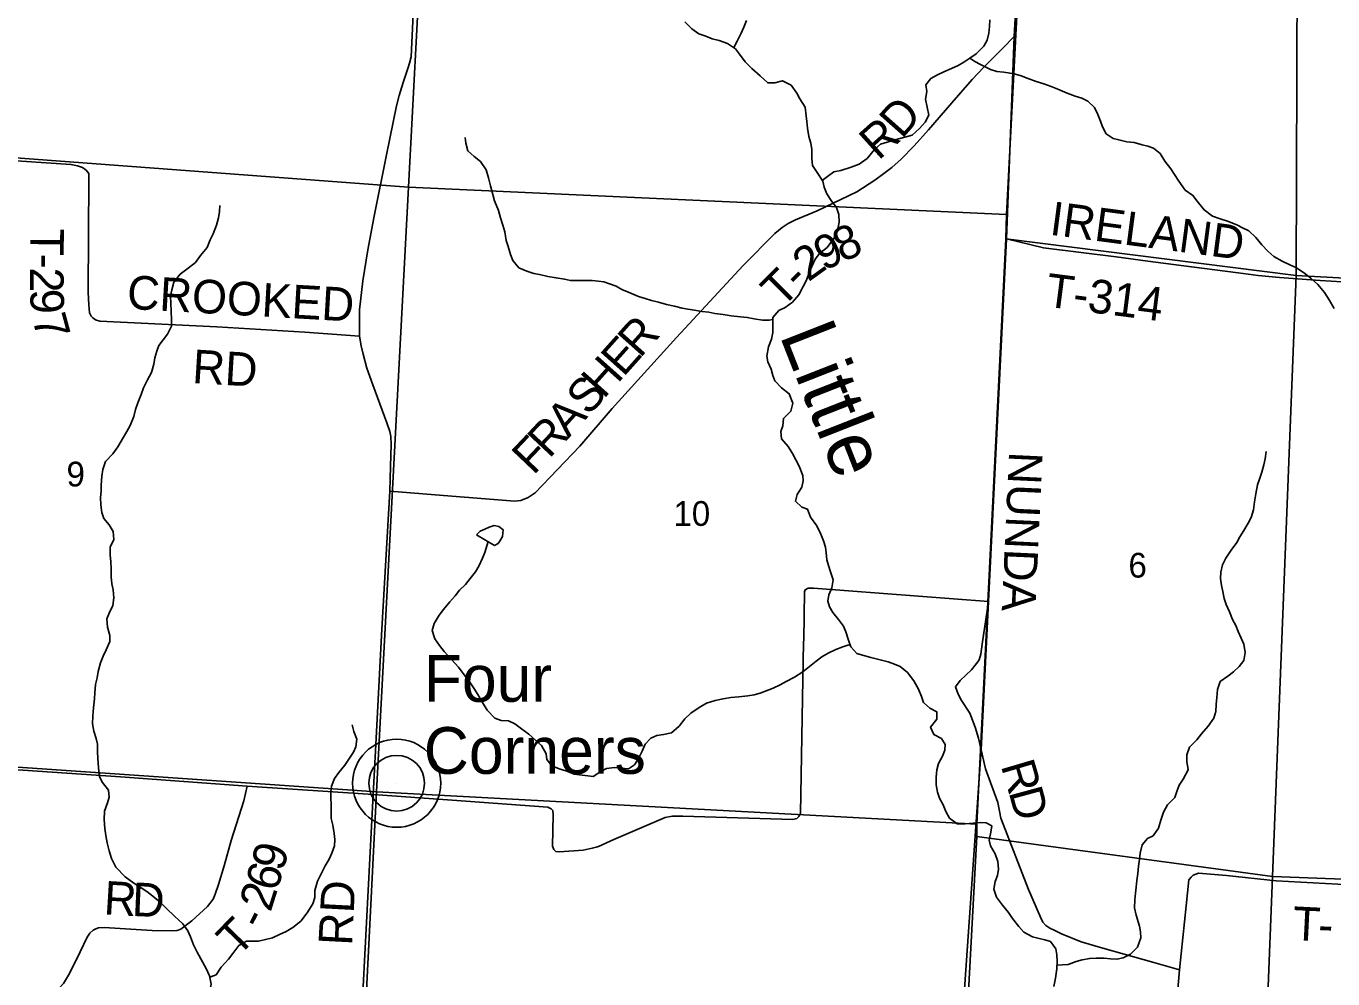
# Model space of a CAD drawing. Extents: x 1759416 to 2214760, y 252598 to 1116833.
# Drawn here: x 1998256 to 2009925, y 911621 to 920128 of the extents above; entities that cross this region are included whole.
import ezdxf

# ---------------------------------------------------------------- set-up
doc = ezdxf.new("R2010")
doc.units = 0
for name, color, linetype in [('GM_X_County_Road', 7, 'Continuous'), ('GM_X_County_Road_Text', 7, 'Continuous'), ('GM_X_Minor_Lake', 7, 'Continuous'), ('GM_X_Minor_River', 7, 'Continuous'), ('GM_X_Minor_River_Text', 7, 'Continuous'), ('GM_X_Section', 7, 'Continuous'), ('GM_X_Section_Text', 7, 'Continuous'), ('GM_X_Township', 7, 'Continuous'), ('GM_X_Township_Road', 7, 'Continuous'), ('GM_X_Township_Road_Text', 7, 'Continuous'), ('GM_X_Unincorporated', 7, 'Continuous'), ('GM_X_Unincorporated_Location', 7, 'Continuous'), ('GM_X_Unincorporated_Text', 7, 'Continuous')]:
    doc.layers.add(name, color=color, linetype=linetype)

msp = doc.modelspace()

# ---------------------------------------------------------------- linework, layer by layer
at = {"layer": 'GM_X_County_Road'}
for points in [[(2006766, 914471), (2006782, 914521), (2006794, 914611), (2006850, 914992), (2007010, 918229), (2007080, 920037), (2007121, 920797), (2007263, 923436), (2007268, 923555)], [(2001192, 910125), (2001356, 913267), (2001379, 913714), (2001432, 914744), (2001505, 915975), (2001510, 916196), (2001517, 916394), (2001514, 916463), (2001504, 916509), (2001477, 916585), (2001351, 916925), (2001300, 917074), (2001265, 917198), (2001247, 917275), (2001232, 917359), (2001232, 917425), (2001234, 917596), (2001263, 917854), (2001307, 918131), (2001364, 918431), (2001473, 918980), (2001563, 919416), (2001587, 919509), (2001624, 919625), (2001669, 919759), (2001681, 919799), (2001694, 919855), (2001719, 920366)], [(2008491, 910937), (2008556, 911703), (2008327, 911768), (2007871, 911894), (2007678, 911951), (2007502, 912024), (2007436, 912055), (2007398, 912075), (2007363, 912099), (2007335, 912127), (2007313, 912172), (2007207, 912420), (2006959, 913055), (2006933, 913196), (2006822, 913496), (2006784, 913665), (2006760, 913769), (2006731, 913868), (2006683, 913993), (2006608, 914108), (2006579, 914163), (2006555, 914230), (2006596, 914284), (2006697, 914379), (2006731, 914423), (2006753, 914452), (2006765, 914469), (2006766, 914471)]]:
    msp.add_lwpolyline(points, dxfattribs=at)
at = {"layer": 'GM_X_Minor_Lake'}
for points in [[(2002440, 915492), (2002472, 915510), (2002488, 915534), (2002509, 915571), (2002515, 915631), (2002477, 915659), (2002435, 915668), (2002391, 915654), (2002353, 915636), (2002311, 915620), (2002279, 915586)], [(2002279, 915586), (2002440, 915492)]]:
    msp.add_lwpolyline(points, dxfattribs=at)
at = {"layer": 'GM_X_Minor_River'}
for points in [[(2004138, 920168), (2004202, 920104), (2004264, 920060), (2004326, 920040), (2004382, 920016), (2004446, 920000), (2004518, 919973), (2004590, 919927), (2004626, 919877), (2004678, 919809), (2004736, 919751), (2004812, 919685), (2004878, 919621), (2004942, 919623), (2005010, 919641), (2005088, 919601), (2005138, 919531), (2005164, 919478), (2005214, 919404), (2005222, 919328), (2005228, 919278), (2005234, 919216), (2005246, 919144), (2005262, 919084), (2005272, 919026), (2005272, 918946), (2005279, 918884), (2005319, 918820), (2005369, 918744), (2005383, 918689), (2005405, 918631), (2005451, 918563), (2005491, 918509), (2005513, 918445), (2005515, 918377), (2005497, 918293), (2005469, 918231), (2005409, 918153), (2005343, 918101), (2005303, 918047), (2005272, 917981), (2005248, 917929), (2005224, 917859), (2005194, 917803), (2005156, 917730), (2005100, 917664), (2005034, 917616), (2004978, 917588), (2004924, 917528), (2004923, 917462), (2004925, 917392), (2004911, 917334), (2004885, 917264), (2004871, 917182), (2004879, 917132), (2004909, 917064), (2004925, 917010), (2004941, 916960), (2005001, 916900), (2005071, 916846), (2005103, 916761), (2005085, 916689), (2005019, 916625), (2005013, 916559), (2004995, 916509), (2005002, 916443), (2005060, 916375), (2005100, 916313), (2005130, 916257), (2005160, 916199), (2005192, 916117), (2005196, 916067), (2005182, 916012), (2005140, 915946), (2005126, 915886), (2005184, 915834), (2005234, 915816), (2005260, 915744), (2005318, 915666), (2005354, 915592), (2005376, 915532), (2005394, 915476), (2005400, 915426), (2005406, 915364), (2005420, 915312), (2005438, 915257)], [(2004575, 919937), (2004606, 919993), (2004642, 920066), (2004666, 920120), (2004688, 920178)], [(2005365, 918751), (2005411, 918786), (2005470, 918828), (2005532, 918840), (2005624, 918868), (2005694, 918897), (2005766, 918947), (2005832, 919028), (2005886, 919074), (2006026, 919116), (2006103, 919138), (2006167, 919155), (2006233, 919214), (2006283, 919272), (2006317, 919334), (2006301, 919404), (2006287, 919476), (2006299, 919544), (2006291, 919604), (2006335, 919662), (2006394, 919692), (2006450, 919720), (2006520, 919750), (2006578, 919776), (2006630, 919806), (2006684, 919842), (2006740, 919882), (2006808, 919948), (2006838, 920002), (2006852, 920066), (2006858, 920124), (2006863, 920184)], [(2006684, 919842), (2006728, 919812), (2006778, 919786), (2006868, 919740), (2006924, 919724), (2006986, 919718), (2007042, 919708), (2007092, 919700), (2007142, 919685), (2007196, 919665), (2007276, 919635), (2007344, 919613), (2007410, 919589), (2007469, 919565), (2007551, 919529), (2007625, 919503), (2007683, 919485), (2007737, 919459), (2007797, 919403), (2007825, 919339), (2007851, 919279), (2007867, 919228), (2007899, 919168), (2007963, 919124), (2008013, 919112), (2008085, 919096), (2008149, 919090), (2008221, 919068), (2008273, 919056), (2008323, 919038), (2008383, 918990), (2008425, 918922), (2008477, 918854), (2008511, 918802), (2008549, 918743), (2008607, 918665), (2008675, 918617), (2008713, 918565), (2008775, 918487), (2008851, 918431), (2008917, 918409), (2008985, 918387), (2009067, 918355), (2009117, 918327), (2009175, 918299), (2009237, 918240), (2009291, 918176), (2009345, 918120), (2009399, 918072), (2009473, 918030), (2009539, 917998), (2009593, 917974), (2009661, 917928), (2009727, 917878), (2009789, 917822), (2009849, 917749), (2009891, 917683), (2009937, 917607)], [(2003312, 917858), (2003116, 917857), (2003064, 917869), (2002988, 917880), (2002914, 917894), (2002839, 917910), (2002789, 917919), (2002727, 917939), (2002657, 917971), (2002601, 918035), (2002582, 918089), (2002560, 918161), (2002544, 918215), (2002530, 918293), (2002513, 918351), (2002493, 918417), (2002473, 918483), (2002440, 918567), (2002424, 918625), (2002402, 918701), (2002385, 918775), (2002365, 918845), (2002315, 918919), (2002258, 918965), (2002200, 919014), (2002184, 919082), (2002176, 919133)], [(1999985, 918528), (1999983, 918474), (1999973, 918416), (1999956, 918352), (1999926, 918273), (1999900, 918219), (1999872, 918153), (1999813, 918080), (1999769, 918018), (1999703, 917966), (1999633, 917915), (1999574, 917843), (1999556, 917775), (1999546, 917719), (1999548, 917649), (1999551, 917589), (1999555, 917500), (1999555, 917448), (1999518, 917378), (1999480, 917328), (1999442, 917276), (1999424, 917225), (1999406, 917167), (1999397, 917109), (1999375, 917035), (1999341, 916969), (1999305, 916900), (1999284, 916838), (1999254, 916766), (1999234, 916706), (1999217, 916644), (1999185, 916563), (1999157, 916509), (1999127, 916459), (1999074, 916371), (1999030, 916308), (1998966, 916242), (1998942, 916170), (1998933, 916110), (1998927, 916029), (1998925, 915975), (1998921, 915919), (1998922, 915853), (1998932, 915785), (1998950, 915733), (1998997, 915675), (1999035, 915615), (1999041, 915543), (1999007, 915475), (1999008, 915403), (1999012, 915349), (1999016, 915283), (1999017, 915211), (1999021, 915147), (1999033, 915094), (1999040, 915022), (1999030, 914956), (1998998, 914886), (1998978, 914836), (1998983, 914760), (1999003, 914688), (1999003, 914632), (1998971, 914559), (1998944, 914503), (1998920, 914443), (1998900, 914367), (1998891, 914309), (1998877, 914249), (1998869, 914176), (1998867, 914122), (1998858, 914040), (1998852, 913970), (1998850, 913898), (1998861, 913832), (1998883, 913768), (1998893, 913716), (1998895, 913646), (1998898, 913596), (1998900, 913544), (1998906, 913476), (1998912, 913425), (1998939, 913373), (1998991, 913306), (1998997, 913244), (1998983, 913193), (1998956, 913119), (1998954, 913043), (1998960, 912963), (1998969, 912901), (1998981, 912835), (1998997, 912763), (1999018, 912695), (1999058, 912617), (1999142, 912531), (1999217, 912475), (1999285, 912434), (1999335, 912400), (1999389, 912358), (1999456, 912304), (1999510, 912248), (1999582, 912181)], [(2004924, 917510), (2004892, 917504), (2004831, 917504), (2004757, 917516), (2004695, 917527), (2004635, 917533), (2004551, 917541), (2004479, 917553), (2004407, 917563), (2004353, 917573), (2004291, 917579), (2004225, 917591), (2004165, 917601), (2004115, 917611), (2004045, 917627), (2003975, 917643), (2003903, 917663), (2003841, 917679), (2003783, 917695), (2003725, 917713), (2003640, 917749), (2003576, 917778), (2003526, 917806), (2003466, 917828), (2003416, 917844), (2003364, 917852), (2003312, 917858)], [(2007461, 911742), (2007562, 911750), (2007632, 911776), (2007686, 911790), (2007754, 911804), (2007812, 911806), (2007884, 911806), (2007940, 911800), (2007996, 911796), (2008051, 911808), (2008119, 911842), (2008179, 911904), (2008211, 911988), (2008207, 912042), (2008197, 912092), (2008167, 912190), (2008153, 912254), (2008157, 912328), (2008163, 912386), (2008167, 912440), (2008173, 912500), (2008183, 912563), (2008190, 912627), (2008198, 912689), (2008204, 912743), (2008222, 912817), (2008270, 912873), (2008320, 912899), (2008368, 912967), (2008390, 913039), (2008412, 913111), (2008448, 913175), (2008513, 913241), (2008531, 913293), (2008551, 913351), (2008587, 913405), (2008633, 913487), (2008621, 913561), (2008621, 913620), (2008645, 913690), (2008711, 913756), (2008751, 913810), (2008812, 913878), (2008862, 913948), (2008880, 914008), (2008884, 914072), (2008888, 914132), (2008896, 914204), (2008918, 914276), (2008986, 914324), (2009036, 914364), (2009088, 914410), (2009131, 914464), (2009143, 914536), (2009131, 914610), (2009107, 914664), (2009079, 914722), (2009057, 914775), (2009029, 914831), (2009003, 914899), (2008973, 914965), (2008953, 915017), (2008941, 915079), (2008931, 915133), (2008921, 915195), (2008923, 915253), (2008939, 915319), (2008969, 915379), (2009016, 915449), (2009068, 915517), (2009094, 915567), (2009130, 915625), (2009168, 915690), (2009196, 915742), (2009216, 915810), (2009224, 915880), (2009236, 915952), (2009252, 916032), (2009271, 916084), (2009289, 916146), (2009309, 916212), (2009321, 916264), (2009329, 916330)], [(2003321, 913429), (2003149, 913448), (2003075, 913480), (2003015, 913496), (2002951, 913522), (2002906, 913579), (2002900, 913629), (2002858, 913705), (2002808, 913749), (2002745, 913805), (2002681, 913855), (2002619, 913897), (2002563, 913924), (2002499, 913928), (2002442, 913950), (2002372, 914020), (2002332, 914088), (2002291, 914160), (2002253, 914217), (2002219, 914269), (2002169, 914337), (2002116, 914405), (2002054, 914473), (2001990, 914543), (2001947, 914597), (2001905, 914657), (2001883, 914733), (2001900, 914793), (2001944, 914869), (2001984, 914919), (2002040, 914988), (2002087, 915040), (2002127, 915092), (2002179, 915143), (2002221, 915197), (2002269, 915255), (2002298, 915305), (2002332, 915378), (2002352, 915428), (2002381, 915526)], [(2005438, 915257), (2005462, 915183), (2005451, 915113), (2005423, 915051), (2005415, 914993), (2005429, 914943), (2005459, 914893), (2005511, 914829), (2005555, 914769), (2005577, 914719), (2005599, 914645), (2005621, 914587), (2005675, 914526), (2005725, 914510), (2005799, 914490), (2005893, 914466), (2005955, 914452), (2006011, 914430), (2006061, 914410), (2006125, 914356), (2006183, 914282), (2006225, 914208), (2006251, 914142), (2006269, 914088), (2006325, 914037), (2006389, 914005), (2006389, 913941), (2006333, 913869), (2006363, 913803), (2006429, 913767), (2006463, 913713), (2006459, 913663), (2006439, 913611), (2006403, 913543), (2006387, 913489), (2006381, 913423), (2006382, 913355), (2006394, 913289), (2006412, 913236), (2006444, 913174), (2006470, 913114), (2006502, 913056), (2006570, 913004), (2006640, 913004), (2006714, 913012), (2006777, 913018), (2006829, 913014), (2006879, 912986), (2006871, 912932), (2006856, 912860), (2006868, 912810), (2006908, 912738), (2006934, 912668), (2006938, 912601), (2006930, 912545), (2006910, 912489), (2006898, 912421), (2006922, 912351), (2006974, 912279), (2007028, 912213), (2007064, 912161), (2007120, 912089), (2007166, 912037), (2007242, 911997), (2007302, 911982), (2007352, 911970), (2007402, 911954), (2007450, 911888), (2007460, 911836), (2007462, 911778), (2007460, 911712), (2007448, 911628), (2007434, 911554)], [(2005617, 914598), (2005603, 914603), (2005549, 914587), (2005487, 914563), (2005417, 914529), (2005361, 914497), (2005311, 914459), (2005252, 914411), (2005192, 914363), (2005118, 914315), (2005042, 914277), (2004988, 914247), (2004926, 914217), (2004810, 914173), (2004756, 914157), (2004700, 914147), (2004619, 914139), (2004549, 914133), (2004479, 914123), (2004409, 914107), (2004333, 914083), (2004265, 914045), (2004193, 913993), (2004137, 913943), (2004087, 913877), (2004019, 913817), (2003948, 913803), (2003888, 913795), (2003836, 913769), (2003784, 913717), (2003756, 913653), (2003724, 913589), (2003688, 913533), (2003636, 913497), (2003566, 913503), (2003510, 913507), (2003440, 913499), (2003389, 913473), (2003321, 913429)], [(1999896, 911636), (1999953, 911657), (1999997, 911724), (2000064, 911798), (2000102, 911848), (2000156, 911919), (2000224, 911957), (2000330, 911958), (2000382, 911970), (2000456, 911986), (2000518, 912016), (2000578, 912045), (2000637, 912081), (2000709, 912137), (2000767, 912210), (2000817, 912292), (2000834, 912348), (2000834, 912410), (2000858, 912493), (2000897, 912571), (2000927, 912629), (2000963, 912691), (2000987, 912744), (2001009, 912808), (2001012, 912866), (2001008, 912920), (2000994, 912994), (2000981, 913054), (2000979, 913106), (2000979, 913178), (2000977, 913238), (2000978, 913292), (2000984, 913343), (2001010, 913411), (2001048, 913463), (2001101, 913529), (2001137, 913584), (2001179, 913644), (2001201, 913694), (2001210, 913760), (2001184, 913830), (2001168, 913890)], [(1999582, 912181), (1999655, 912111), (1999701, 912049), (1999723, 911995), (1999752, 911925), (1999784, 911859), (1999865, 911715), (1999893, 911649), (1999909, 911575), (1999897, 911517), (1999882, 911467), (1999864, 911415), (1999844, 911350), (1999826, 911284), (1999811, 911224), (1999779, 911154), (1999757, 911096), (1999747, 911044), (1999742, 910977), (1999742, 910915), (1999736, 910843), (1999729, 910777), (1999721, 910697), (1999713, 910643)]]:
    msp.add_lwpolyline(points, dxfattribs=at)
at = {"layer": 'GM_X_Section'}
for points in [[(1999174, 923993), (2001942, 923819), (2001672, 918691), (1996050, 919111), (1996368, 924167)], [(2004585, 923695), (2007271, 923556), (2007269, 923432), (2007011, 918447), (2001672, 918691), (2001942, 923819)], [(2009616, 923329), (2009597, 917901), (2007004, 918229), (2007011, 918447), (2007269, 923432)], [(2009779, 923321), (2012310, 923218), (2014844, 923116), (2014894, 917612), (2009597, 917901), (2009616, 923329), (2009642, 923327)], [(2001672, 918691), (2001384, 913291), (1995713, 913681), (1996050, 919111)], [(2007011, 918447), (2007004, 918229), (2006745, 913001), (2001384, 913291), (2001672, 918691)], [(2007004, 918229), (2009597, 917901), (2009385, 912536), (2006747, 912893), (2006745, 913001)], [(2014894, 917612), (2014681, 912335), (2009385, 912536), (2009597, 917901)], [(1995713, 913681), (2001384, 913291), (2001110, 907846), (1995356, 908258)], [(2001384, 913291), (2006745, 913001), (2006747, 912893), (2006459, 907572), (2001110, 907846)], [(2006747, 912893), (2009385, 912536), (2009177, 907246), (2006448, 907374), (2006459, 907572)], [(2009385, 912536), (2014681, 912335), (2014469, 906993), (2009177, 907246)]]:
    msp.add_lwpolyline(points, close=True, dxfattribs=at)
at = {"layer": 'GM_X_Township'}
for points in [[(2007121, 920797), (2007080, 920037), (2007010, 918229), (2006850, 914992), (2006784, 913665), (2006572, 910634), (2006421, 907543), (2006290, 903477), (2006227, 902002), (2006118, 899457), (2006004, 896755), (2003205, 896913), (1999329, 897063), (1998108, 897126)], [(2006290, 903477), (2006421, 907543), (2006572, 910634), (2006784, 913665), (2006850, 914992), (2007010, 918229), (2007080, 920037), (2007121, 920797)]]:
    msp.add_lwpolyline(points, dxfattribs=at)
at = {"layer": 'GM_X_Township_Road'}
for points in [[(2007080, 920037), (2006979, 919931), (2006807, 919762), (2006704, 919651), (2006523, 919444), (2006313, 919203), (2006186, 919060), (2006069, 918941), (2005986, 918867), (2005916, 918812), (2005836, 918752), (2005673, 918649), (2005319, 918479), (2005125, 918399), (2005062, 918367), (2005008, 918331), (2004942, 918276), (2004660, 917992), (2004063, 917347), (2003490, 916713), (2003202, 916377), (2002803, 915961), (2002739, 915919), (2002673, 915893), (2002619, 915888), (2001983, 915936), (2001505, 915975)], [(2001232, 917359), (2000746, 917396), (1999958, 917444), (1998916, 917495), (1998876, 917505), (1998852, 917523), (1998836, 917539), (1998822, 917568), (1998815, 917640), (1998811, 917754), (1998816, 918775), (1998815, 918813), (1998793, 918841), (1998761, 918866), (1998715, 918882), (1998657, 918894), (1997551, 918966)], [(2007010, 918229), (2007341, 918150), (2007991, 918069), (2008273, 918031), (2008569, 917992), (2009079, 917925), (2009257, 917901), (2009447, 917884), (2009811, 917856), (2010008, 917846), (2010050, 917844)], [(2005200, 914650), (2005207, 915078), (2005213, 915096), (2005239, 915110), (2005287, 915109), (2006850, 914992)], [(1991677, 914563), (1991790, 914494), (1991860, 914447), (1991904, 914413), (1991924, 914380), (1991934, 914356), (1991933, 914308), (1991922, 914144), (1991926, 914086), (1991929, 914039), (1991965, 913995), (1991985, 913969), (1992033, 913934), (1992093, 913916), (1992601, 913879), (1993751, 913795), (1994345, 913743), (1994655, 913722), (1995937, 913636), (1997265, 913551), (1999099, 913426), (2000229, 913342), (2001356, 913267)], [(2001356, 913267), (2002060, 913216), (2002916, 913154), (2002946, 913138), (2002960, 913124), (2002963, 913087), (2002957, 912807), (2002969, 912777), (2002987, 912758), (2003019, 912756), (2003231, 912771), (2003311, 912788), (2003345, 912796), (2003366, 912803), (2003504, 912864), (2003962, 913061), (2004026, 913074), (2004120, 913074), (2005104, 913045), (2005138, 913053), (2005157, 913071), (2005171, 913101), (2005193, 914295), (2005199, 914626), (2005200, 914650)], [(2000229, 913342), (2000199, 913210), (2000088, 912858), (2000024, 912630), (1999973, 912464), (1999945, 912378), (1999926, 912334), (1999876, 912266), (1999737, 912140), (1999638, 912065), (1999606, 912053), (1999560, 912049), (1999382, 912054), (1998952, 912079), (1998902, 912076), (1998880, 912068), (1998854, 912056), (1998826, 912030), (1998801, 911994), (1998738, 911862), (1998645, 911668), (1998590, 911580), (1998308, 911275), (1997836, 910787)], [(2008556, 911703), (2008615, 912274), (2008640, 912504), (2008658, 912530), (2008676, 912548), (2008726, 912564), (2008974, 912544), (2009418, 912495), (2009968, 912466), (2010094, 912464), (2010142, 912472), (2010290, 912504), (2010424, 912531), (2010463, 912539), (2010499, 912531), (2010525, 912523), (2010701, 912470), (2010769, 912449), (2010872, 912428), (2011209, 912425), (2011293, 912406)]]:
    msp.add_lwpolyline(points, dxfattribs=at)
at = {"layer": 'GM_X_Unincorporated'}
for radius in [393, 249]:
    msp.add_circle((2001565, 913368), radius, dxfattribs=at)
at = {"layer": 'GM_X_Unincorporated_Location'}
msp.add_line((2001565, 913368), (2001565, 913368), dxfattribs=at)

# ---------------------------------------------------------------- texts
at = {"layer": 'GM_X_County_Road_Text'}
for s, rotation, p in [('NUNDA', 267.337, (2007034, 916333)), ('R', 286.4574, (2006958, 913526)), ('D', 285.2158, (2007028, 913291)), ('RD', 87.0388, (2001166, 911914))]:
    msp.add_text(s, height=300, rotation=rotation, dxfattribs=at).set_placement(p)
at = {"layer": 'GM_X_Minor_River_Text'}
msp.add_text('Little', height=500.1, rotation=291.4287, dxfattribs=at).set_placement((2004981, 917370))
at = {"layer": 'GM_X_Section_Text'}
for s, p in [('9', (1998617, 916018)), ('10', (2004036, 915666)), ('6', (2008099, 915204))]:
    msp.add_text(s, height=221, rotation=0, dxfattribs=at).set_placement(p)
at = {"layer": 'GM_X_Township_Road_Text'}
for s, rotation, p in [('D', 48.4569, (2006075, 919114)), ('R', 42.0429, (2005867, 918923)), ('IRELAND', 352.4879, (2007388, 918267)), ('T', 269.5543, (1998294, 918323)), ('8', 24.2489, (2005545, 918016)), ('2', 35.7603, (2005241, 917840)), ('9', 24.2954, (2005377, 917940)), ('-', 269.5967, (1998293, 918098)), ('2', 269.7677, (1998292, 917974)), ('T', 44.9879, (2005004, 917603)), ('-', 44.8234, (2005163, 917761)), ('CROOKED', 356.7331, (1999152, 917605)), ('T-314', 352.6653, (2007350, 917626)), ('9', 271.962, (1998291, 917777)), ('7', 285.1554, (1998309, 917518)), ('R', 48.2425, (2003738, 917157)), ('E', 48.2412, (2003589, 916989)), ('RD', 356.6039, (1999735, 916942)), ('H', 48.242, (2003413, 916792)), ('S', 48.2261, (2003278, 916641)), ('A', 47.7493, (2003099, 916444)), ('R', 46.8668, (2002927, 916260)), ('F', 46.4919, (2002786, 916112)), ('9', 74.1421, (2000549, 912572)), ('6', 73.6203, (2000496, 912391)), ('R', 356.618, (1998945, 912197)), ('D', 357.5426, (1999197, 912183)), ('2', 72.6509, (2000439, 912210)), ('T', 357.1361, (2009561, 911969)), ('T', 45.4758, (2000146, 911808)), ('-', 62.6423, (2000361, 912048)), ('-', 357.7325, (2009789, 911958))]:
    msp.add_text(s, height=300, rotation=rotation, dxfattribs=at).set_placement(p)
at = {"layer": 'GM_X_Unincorporated_Text'}
for s, p in [('Four', (2001807, 914095)), ('Corners', (2001807, 913452))]:
    msp.add_text(s, height=417, rotation=0, dxfattribs=at).set_placement(p)

doc.saveas('drawing.dxf')
